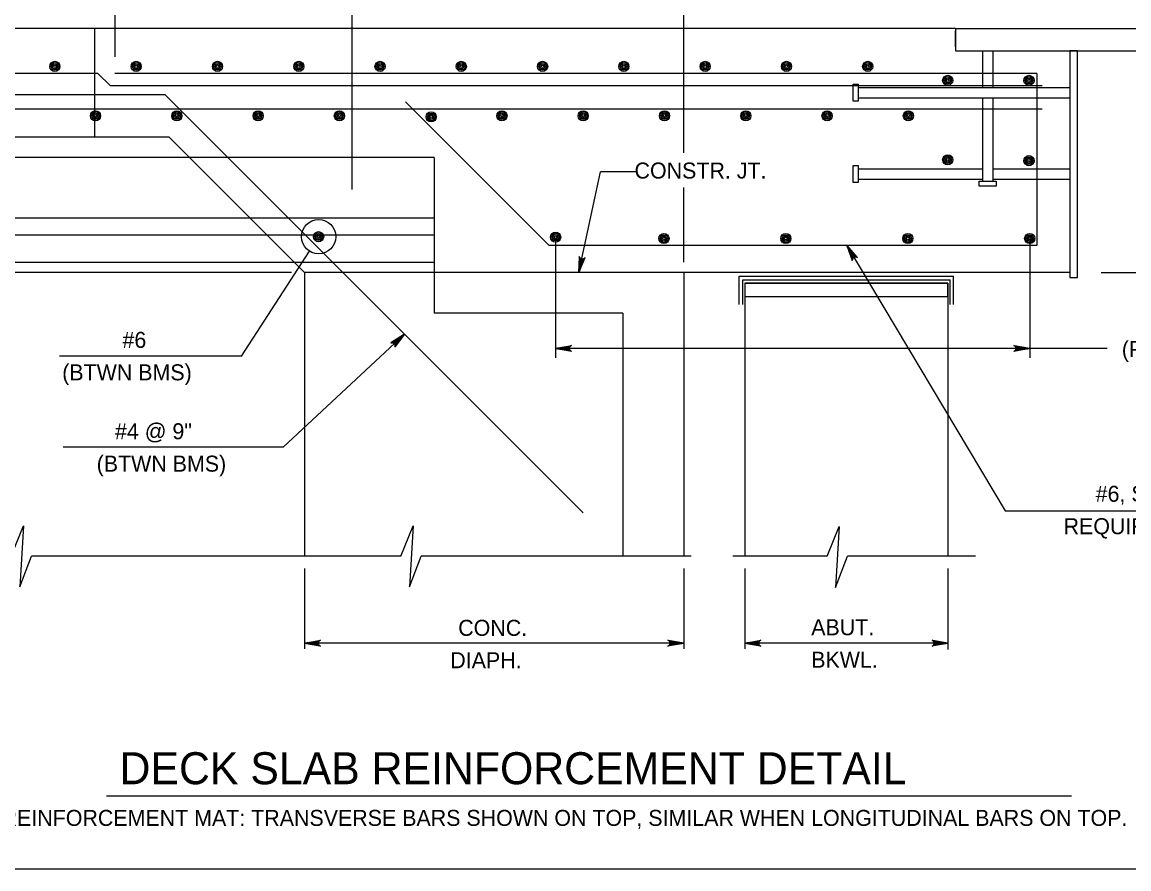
# Model space of a CAD drawing. Extents: x 636530 to 644067, y 294168 to 299122.
# Drawn here: x 639183.1 to 639390.6, y 294777.5 to 294936.2 of the extents above; entities that cross this region are included whole.
import ezdxf

# ---------------------------------------------------------------- set-up
doc = ezdxf.new("R2010")
doc.units = 0
doc.layers.add('1', color=7, linetype='Continuous')

msp = doc.modelspace()

# ---------------------------------------------------------------- linework, layer by layer
at = {"layer": '1'}
for p, q in [((639200.52, 294961.25), (639200.52, 294929.72)), ((639307.2, 294911.7), (639307.2, 294961.25)), ((639244.97, 294947.03), (639244.97, 294904.84)), ((639358.15, 294934.99), (639160.17, 294934.99)), ((639196.71, 294934.99), (639196.71, 294914.67)), ((639358.15, 294934.99), (639358.15, 294930.86)), ((639358.15, 294934.99), (639395.88, 294934.99)), ((639358.15, 294930.86), (639395.88, 294930.86)), ((639363.23, 294930.86), (639363.23, 294923.94)), ((639365.14, 294930.86), (639365.14, 294923.94)), ((639197.34, 294926.6), (639160.17, 294926.6)), ((639199.68, 294924.26), (639197.34, 294926.6)), ((639373.38, 294926.6), (639200.52, 294926.6)), ((639373.38, 294926.6), (639373.38, 294894.35)), ((639374.37, 294924.26), (639199.68, 294924.26)), ((639339.91, 294923.94), (639379.59, 294923.94)), ((639209.97, 294922.57), (639177.37, 294922.57)), ((639288.34, 294844.2), (639209.97, 294922.57)), ((639281.94, 294894.35), (639255, 294921.29)), ((639339.91, 294922.03), (639379.59, 294922.03)), ((639363.23, 294922.03), (639363.23, 294912.45)), ((639365.14, 294922.03), (639365.14, 294912.45)), ((639374.37, 294919.89), (639160.17, 294919.89)), ((639210.68, 294914.67), (639160.17, 294914.67)), ((639236.08, 294889.27), (639210.68, 294914.67)), ((639214.49, 294910.86), (639160.17, 294910.86)), ((639260.42, 294910.86), (639214.49, 294910.86)), ((639260.42, 294910.86), (639260.42, 294881.65)), ((639363.23, 294912.45), (639363.23, 294906.42)), ((639365.14, 294912.45), (639365.14, 294906.42)), ((639339.91, 294908.7), (639363.23, 294908.7)), ((639365.14, 294908.7), (639379.59, 294908.7)), ((639287.52, 294889.27), (639291.57, 294908.16)), ((639298.25, 294908.16), (639291.57, 294908.16)), ((639339.91, 294906.79), (639363.23, 294906.79)), ((639365.14, 294906.79), (639379.59, 294906.79)), ((639307.2, 294891.2), (639307.2, 294905.2)), ((639225.92, 294899.43), (639163.37, 294899.43)), ((639260.42, 294899.43), (639225.92, 294899.43)), ((639229.1, 294896.25), (639160.17, 294896.25)), ((639260.42, 294896.25), (639229.1, 294896.25)), ((639238.73, 294895.99), (639238.73, 294895.99)), ((639373.38, 294894.35), (639281.94, 294894.35)), ((639283.16, 294895.64), (639283.16, 294873.27)), ((639337.75, 294894.35), (639367.47, 294844.59)), ((639372.06, 294895.64), (639372.06, 294873.27)), ((639224.25, 294873.57), (639236.99, 294893.3)), ((639234.18, 294891.17), (639160.17, 294891.17)), ((639260.42, 294891.17), (639234.18, 294891.17)), ((639233.64, 294889.27), (639128.73, 294889.27)), ((639307.2, 294889.27), (639236.08, 294889.27)), ((639236.08, 294889.27), (639236.08, 294836.08)), ((639379.59, 294889.27), (639307.2, 294889.27)), ((639307.2, 294889.27), (639307.2, 294836.08)), ((639317.6, 294888.56), (639357.76, 294888.56)), ((639317.6, 294883.26), (639317.6, 294888.56)), ((639318.24, 294887.93), (639357.13, 294887.93)), ((639318.24, 294883.26), (639318.24, 294887.93)), ((639357.13, 294883.26), (639357.13, 294887.93)), ((639357.76, 294883.26), (639357.76, 294888.56)), ((639385.47, 294889.27), (639410.98, 294889.27)), ((639318.63, 294887.29), (639318.63, 294836.08)), ((639318.63, 294887.29), (639356.73, 294887.29)), ((639356.73, 294887.29), (639356.73, 294836.08)), ((639318.63, 294884.75), (639356.73, 294884.75)), ((639295.77, 294881.65), (639260.42, 294881.65)), ((639295.77, 294881.65), (639295.77, 294836.08)), ((639254.83, 294877.71), (639232.05, 294856.53)), ((639224.25, 294873.57), (639190.12, 294873.57)), ((639386.58, 294875.04), (639283.16, 294875.04)), ((639232.05, 294856.53), (639190.84, 294856.53)), ((639367.47, 294844.59), (639435.03, 294844.59)), ((639254.14, 294836.08), (639184.87, 294836.08)), ((639308.55, 294836.08), (639257.95, 294836.08)), ((639334.08, 294836.08), (639316.38, 294836.08)), ((639361.87, 294836.08), (639337.88, 294836.08)), ((639236.08, 294833.79), (639236.08, 294818.75)), ((639307.2, 294833.79), (639307.2, 294818.75)), ((639318.63, 294833.79), (639318.63, 294818.75)), ((639356.73, 294833.79), (639356.73, 294818.62)), ((639307.2, 294819.78), (639236.08, 294819.78)), ((639356.73, 294819.78), (639318.63, 294819.78)), ((639198.93, 294791.15), (639379.9, 294791.15)), ((639046.78, 294777.48), (639832.78, 294777.48))]:
    msp.add_line(p, q, dxfattribs=at)
for points in [[(639358.15, 294931.56), (639358.15, 294934.6)], [(639337.75, 294894.35), (639338.79, 294891.5), (639338.8, 294891.64), (639338.81, 294891.78), (639338.87, 294891.88), (639338.92, 294891.98), (639339, 294892.05), (639339.08, 294892.12), (639339.17, 294892.15), (639339.27, 294892.19), (639339.38, 294892.19), (639339.5, 294892.19), (639339.63, 294892.13), (639339.75, 294892.07), (639337.75, 294894.35), (639339.63, 294892.13), (639339.5, 294892.19), (639337.75, 294894.35), (639339.38, 294892.19), (639339.27, 294892.19), (639337.75, 294894.35), (639339.17, 294892.15), (639339.08, 294892.12), (639337.75, 294894.35), (639339, 294892.05), (639338.92, 294891.98), (639337.75, 294894.35), (639338.87, 294891.88), (639338.81, 294891.78), (639337.75, 294894.35), (639338.8, 294891.64)], [(639287.52, 294889.27), (639288.69, 294892.07), (639288.59, 294891.97), (639288.49, 294891.88), (639288.38, 294891.84), (639288.27, 294891.8), (639288.17, 294891.81), (639288.06, 294891.81), (639287.97, 294891.85), (639287.88, 294891.89), (639287.79, 294891.97), (639287.7, 294892.04), (639287.65, 294892.17), (639287.6, 294892.3), (639287.52, 294889.27), (639287.65, 294892.17), (639287.7, 294892.04), (639287.52, 294889.27), (639287.79, 294891.97), (639287.88, 294891.89), (639287.52, 294889.27), (639287.97, 294891.85), (639288.06, 294891.81), (639287.52, 294889.27), (639288.17, 294891.81), (639288.27, 294891.8), (639287.52, 294889.27), (639288.38, 294891.84), (639288.49, 294891.88), (639287.52, 294889.27), (639288.59, 294891.97)], [(639254.83, 294877.71), (639252.27, 294876.08), (639252.41, 294876.1), (639252.54, 294876.12), (639252.66, 294876.09), (639252.77, 294876.06), (639252.85, 294876), (639252.93, 294875.94), (639252.98, 294875.85), (639253.04, 294875.77), (639253.06, 294875.65), (639253.09, 294875.54), (639253.06, 294875.4), (639253.03, 294875.27), (639254.83, 294877.71), (639253.06, 294875.4), (639253.09, 294875.54), (639254.83, 294877.71), (639253.06, 294875.65), (639253.04, 294875.77), (639254.83, 294877.71), (639252.98, 294875.85), (639252.93, 294875.94), (639254.83, 294877.71), (639252.85, 294876), (639252.77, 294876.06), (639254.83, 294877.71), (639252.66, 294876.09), (639252.54, 294876.12), (639254.83, 294877.71), (639252.41, 294876.1)], [(639283.16, 294875.04), (639286.14, 294875.6), (639286.03, 294875.52), (639285.91, 294875.44), (639285.85, 294875.34), (639285.79, 294875.24), (639285.78, 294875.14), (639285.76, 294875.04), (639285.78, 294874.94), (639285.79, 294874.84), (639285.85, 294874.74), (639285.91, 294874.64), (639286.03, 294874.56), (639286.14, 294874.48), (639283.16, 294875.04), (639286.03, 294874.56), (639285.91, 294874.64), (639283.16, 294875.04), (639285.85, 294874.74), (639285.79, 294874.84), (639283.16, 294875.04), (639285.78, 294874.94), (639285.76, 294875.04), (639283.16, 294875.04), (639285.78, 294875.14), (639285.79, 294875.24), (639283.16, 294875.04), (639285.85, 294875.34), (639285.91, 294875.44), (639283.16, 294875.04), (639286.03, 294875.52)], [(639372.06, 294875.04), (639369.08, 294874.48), (639369.19, 294874.56), (639369.31, 294874.64), (639369.37, 294874.74), (639369.43, 294874.84), (639369.44, 294874.94), (639369.46, 294875.04), (639369.44, 294875.14), (639369.43, 294875.24), (639369.37, 294875.34), (639369.31, 294875.44), (639369.19, 294875.52), (639369.08, 294875.6), (639372.06, 294875.04), (639369.19, 294875.52), (639369.31, 294875.44), (639372.06, 294875.04), (639369.37, 294875.34), (639369.43, 294875.24), (639372.06, 294875.04), (639369.44, 294875.14), (639369.46, 294875.04), (639372.06, 294875.04), (639369.44, 294874.94), (639369.43, 294874.84), (639372.06, 294875.04), (639369.37, 294874.74), (639369.31, 294874.64), (639372.06, 294875.04), (639369.19, 294874.56)], [(639181.06, 294836.08), (639183.38, 294841.79), (639182.69, 294830.36), (639184.87, 294836.08)], [(639254.14, 294836.08), (639256.46, 294841.79), (639255.77, 294830.36), (639257.95, 294836.08)], [(639334.08, 294836.08), (639336.34, 294841.65), (639335.65, 294830.22), (639337.88, 294836.08)], [(639236.08, 294819.78), (639239.07, 294820.33), (639238.95, 294820.26), (639238.84, 294820.18), (639238.78, 294820.08), (639238.72, 294819.98), (639238.7, 294819.88), (639238.68, 294819.78), (639238.7, 294819.68), (639238.72, 294819.58), (639238.78, 294819.48), (639238.84, 294819.38), (639238.95, 294819.3), (639239.07, 294819.22), (639236.08, 294819.78), (639238.95, 294819.3), (639238.84, 294819.38), (639236.08, 294819.78), (639238.78, 294819.48), (639238.72, 294819.58), (639236.08, 294819.78), (639238.7, 294819.68), (639238.68, 294819.78), (639236.08, 294819.78), (639238.7, 294819.88), (639238.72, 294819.98), (639236.08, 294819.78), (639238.78, 294820.08), (639238.84, 294820.18), (639236.08, 294819.78), (639238.95, 294820.26)], [(639307.2, 294819.78), (639304.22, 294819.22), (639304.33, 294819.3), (639304.45, 294819.38), (639304.51, 294819.48), (639304.57, 294819.58), (639304.59, 294819.68), (639304.6, 294819.78), (639304.59, 294819.88), (639304.57, 294819.98), (639304.51, 294820.08), (639304.45, 294820.18), (639304.33, 294820.26), (639304.22, 294820.33), (639307.2, 294819.78), (639304.33, 294820.26), (639304.45, 294820.18), (639307.2, 294819.78), (639304.51, 294820.08), (639304.57, 294819.98), (639307.2, 294819.78), (639304.59, 294819.88), (639304.6, 294819.78), (639307.2, 294819.78), (639304.59, 294819.68), (639304.57, 294819.58), (639307.2, 294819.78), (639304.51, 294819.48), (639304.45, 294819.38), (639307.2, 294819.78), (639304.33, 294819.3)], [(639318.63, 294819.78), (639321.61, 294820.33), (639321.5, 294820.26), (639321.39, 294820.18), (639321.33, 294820.08), (639321.27, 294819.98), (639321.25, 294819.88), (639321.23, 294819.78), (639321.25, 294819.68), (639321.27, 294819.58), (639321.33, 294819.48), (639321.39, 294819.38), (639321.5, 294819.3), (639321.61, 294819.22), (639318.63, 294819.78), (639321.5, 294819.3), (639321.39, 294819.38), (639318.63, 294819.78), (639321.33, 294819.48), (639321.27, 294819.58), (639318.63, 294819.78), (639321.25, 294819.68), (639321.23, 294819.78), (639318.63, 294819.78), (639321.25, 294819.88), (639321.27, 294819.98), (639318.63, 294819.78), (639321.33, 294820.08), (639321.39, 294820.18), (639318.63, 294819.78), (639321.5, 294820.26)], [(639356.73, 294819.78), (639353.75, 294819.22), (639353.86, 294819.3), (639353.98, 294819.38), (639354.04, 294819.48), (639354.1, 294819.58), (639354.12, 294819.68), (639354.13, 294819.78), (639354.12, 294819.88), (639354.1, 294819.98), (639354.04, 294820.08), (639353.98, 294820.18), (639353.86, 294820.26), (639353.75, 294820.33), (639356.73, 294819.78), (639353.86, 294820.26), (639353.98, 294820.18), (639356.73, 294819.78), (639354.04, 294820.08), (639354.1, 294819.98), (639356.73, 294819.78), (639354.12, 294819.88), (639354.13, 294819.78), (639356.73, 294819.78), (639354.12, 294819.68), (639354.1, 294819.58), (639356.73, 294819.78), (639354.04, 294819.48), (639353.98, 294819.38), (639356.73, 294819.78), (639353.86, 294819.3)]]:
    msp.add_lwpolyline(points, dxfattribs=at)
for points in [[(639381.01, 294888.32), (639381.01, 294930.86), (639379.59, 294930.86), (639379.59, 294888.32)], [(639338.95, 294921.4), (639338.95, 294924.58), (639339.91, 294924.58), (639339.91, 294921.4)], [(639338.95, 294906.16), (639338.95, 294909.34), (639339.91, 294909.34), (639339.91, 294906.16)], [(639362.59, 294906.42), (639365.77, 294906.42), (639365.77, 294905.46), (639362.59, 294905.46)], [(639318.63, 294884.75), (639356.73, 294884.75), (639356.73, 294887.29), (639318.63, 294887.29)]]:
    msp.add_lwpolyline(points, close=True, dxfattribs=at)
for centre, radius in [((639189.28, 294927.92), 0.952), ((639189.28, 294927.92), 0.714), ((639189.28, 294927.92), 0.476), ((639189.28, 294927.92), 0.238), ((639204.52, 294927.92), 0.952), ((639204.52, 294927.92), 0.714), ((639204.52, 294927.92), 0.476), ((639204.52, 294927.92), 0.238), ((639219.76, 294927.92), 0.952), ((639219.76, 294927.92), 0.714), ((639219.76, 294927.92), 0.476), ((639219.76, 294927.92), 0.238), ((639235, 294927.92), 0.952), ((639235, 294927.92), 0.714), ((639235, 294927.92), 0.476), ((639235, 294927.92), 0.238), ((639250.24, 294927.92), 0.952), ((639250.24, 294927.92), 0.714), ((639250.24, 294927.92), 0.476), ((639250.24, 294927.92), 0.238), ((639265.48, 294927.92), 0.952), ((639265.48, 294927.92), 0.714), ((639265.48, 294927.92), 0.476), ((639265.48, 294927.92), 0.238), ((639280.72, 294927.92), 0.952), ((639280.72, 294927.92), 0.714), ((639280.72, 294927.92), 0.476), ((639280.72, 294927.92), 0.238), ((639295.96, 294927.92), 0.952), ((639295.96, 294927.92), 0.714), ((639295.96, 294927.92), 0.476), ((639295.96, 294927.92), 0.238), ((639311.2, 294927.92), 0.952), ((639311.2, 294927.92), 0.714), ((639311.2, 294927.92), 0.476), ((639311.2, 294927.92), 0.238), ((639326.44, 294927.92), 0.952), ((639326.44, 294927.92), 0.714), ((639326.44, 294927.92), 0.476), ((639326.44, 294927.92), 0.238), ((639341.68, 294927.92), 0.952), ((639341.68, 294927.92), 0.714), ((639341.68, 294927.92), 0.476), ((639341.68, 294927.92), 0.238), ((639356.68, 294925.29), 0.952), ((639356.68, 294925.29), 0.714), ((639356.68, 294925.29), 0.476), ((639356.68, 294925.29), 0.238), ((639371.92, 294925.29), 0.952), ((639371.92, 294925.29), 0.714), ((639371.92, 294925.29), 0.476), ((639371.92, 294925.29), 0.238), ((639196.9, 294918.66), 0.952), ((639196.9, 294918.66), 0.714), ((639196.9, 294918.66), 0.476), ((639212.14, 294918.66), 0.952), ((639212.14, 294918.66), 0.714), ((639212.14, 294918.66), 0.476), ((639227.38, 294918.66), 0.952), ((639227.38, 294918.66), 0.714), ((639227.38, 294918.66), 0.476), ((639242.62, 294918.66), 0.952), ((639242.62, 294918.66), 0.714), ((639242.62, 294918.66), 0.476), ((639259.84, 294918.45), 0.952), ((639259.84, 294918.45), 0.714), ((639273.1, 294918.66), 0.952), ((639273.1, 294918.66), 0.714), ((639273.1, 294918.66), 0.476), ((639288.34, 294918.66), 0.952), ((639288.34, 294918.66), 0.714), ((639288.34, 294918.66), 0.476), ((639303.58, 294918.66), 0.952), ((639303.58, 294918.66), 0.714), ((639303.58, 294918.66), 0.476), ((639318.82, 294918.66), 0.952), ((639318.82, 294918.66), 0.714), ((639318.82, 294918.66), 0.476), ((639334.06, 294918.66), 0.952), ((639334.06, 294918.66), 0.714), ((639334.06, 294918.66), 0.476), ((639349.3, 294918.66), 0.952), ((639349.3, 294918.66), 0.714), ((639349.3, 294918.66), 0.476), ((639196.9, 294918.66), 0.238), ((639212.14, 294918.66), 0.238), ((639227.38, 294918.66), 0.238), ((639242.62, 294918.66), 0.238), ((639259.84, 294918.45), 0.476), ((639259.84, 294918.45), 0.238), ((639273.1, 294918.66), 0.238), ((639288.34, 294918.66), 0.238), ((639303.58, 294918.66), 0.238), ((639318.82, 294918.66), 0.238), ((639334.06, 294918.66), 0.238), ((639349.3, 294918.66), 0.238), ((639356.68, 294910.4), 0.952), ((639356.68, 294910.4), 0.714), ((639356.68, 294910.4), 0.476), ((639371.92, 294910.24), 0.952), ((639371.92, 294910.24), 0.714), ((639371.92, 294910.24), 0.476), ((639356.68, 294910.4), 0.238), ((639371.92, 294910.24), 0.238), ((639238.73, 294895.99), 3.2), ((639238.73, 294895.99), 0.952), ((639238.73, 294895.99), 0.714), ((639238.73, 294895.99), 0.476), ((639238.73, 294895.99), 0.238), ((639283.16, 294895.91), 0.952), ((639283.16, 294895.91), 0.714), ((639283.16, 294895.91), 0.476), ((639283.16, 294895.91), 0.238), ((639303.48, 294895.64), 0.952), ((639303.48, 294895.64), 0.714), ((639326.34, 294895.64), 0.952), ((639326.34, 294895.64), 0.714), ((639349.2, 294895.64), 0.952), ((639349.2, 294895.64), 0.714), ((639372.06, 294895.64), 0.952), ((639372.06, 294895.64), 0.714), ((639303.48, 294895.64), 0.476), ((639303.48, 294895.64), 0.238), ((639326.34, 294895.64), 0.476), ((639326.34, 294895.64), 0.238), ((639349.2, 294895.64), 0.476), ((639349.2, 294895.64), 0.238), ((639372.06, 294895.64), 0.476), ((639372.06, 294895.64), 0.238)]:
    msp.add_circle(centre, radius, dxfattribs=at)

# ---------------------------------------------------------------- texts
for s, height, p in [('CONSTR. JT.', 3, (639297.96, 294906.89)), ('#6', 3, (639201.95, 294875.14)), ('(PLACED PARALLEL', 3, (639389.32, 294873.43)), ('(BTWN BMS)', 3, (639190.65, 294869.06)), ('#4 @ 9"', 3, (639200.55, 294858.01)), ('(BTWN BMS)', 3, (639197.11, 294851.94)), ('#6, SPACING AS', 3, (639384.42, 294846.29)), ('REQUIRED BY DESIGN', 3, (639378.41, 294840.22)), ('CONC.', 3, (639264.9, 294821.16)), ('ABUT.', 3, (639331.09, 294821.27)), ('DIAPH.', 3, (639263.41, 294815.09)), ('BKWL.', 3, (639331.09, 294815.19)), ('DECK SLAB REINFORCEMENT DETAIL', 6, (639201.4, 294793.34)), ('FOR DECK TOP REINFORCEMENT MAT: TRANSVERSE BARS SHOWN ON TOP, SIMILAR WHEN LONGITUDINAL BARS ON TOP.', 3, (639148.08, 294785.53))]:
    msp.add_text(s, height=height, dxfattribs=at).set_placement(p)

doc.saveas('drawing.dxf')
